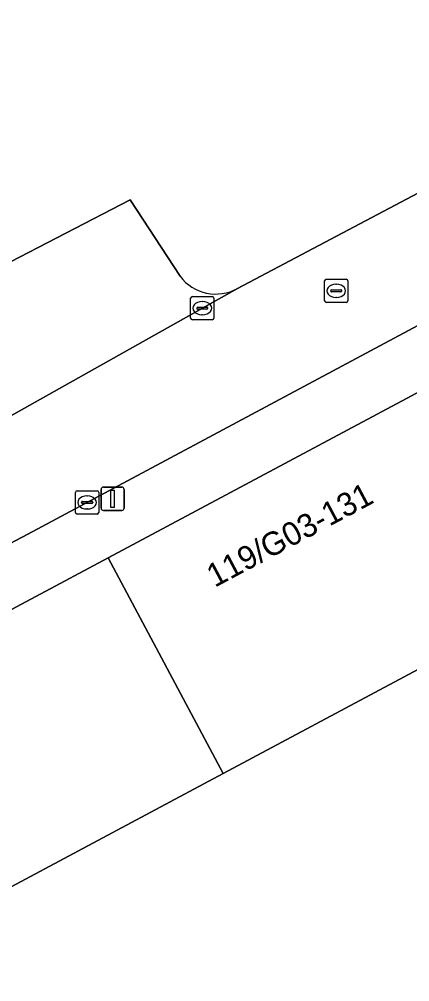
# Model space of a CAD drawing. Extents: x 159674 to 160531, y 382172 to 382904.
# Drawn here: x 159950.09 to 159966.84, y 382325.17 to 382366.41 of the extents above; entities that cross this region are included whole.
import ezdxf

# ---------------------------------------------------------------- set-up
doc = ezdxf.new("R2010")
doc.units = 0
for name, color, linetype in [('IMGEO_Groenvoorziening', 7, 'Continuous'), ('IMGEO_Kolk', 7, 'Continuous'), ('IMGEO_Lichtmast', 7, 'Continuous'), ('IMGEO_Pand', 7, 'Continuous'), ('IMGEO_Pand_nummerreeks', 7, 'Continuous'), ('IMGEO_Parkeervlak_open', 7, 'Continuous'), ('IMGEO_Rijbaan_lokaal_open', 7, 'Continuous'), ('IMGEO_Rioolput', 7, 'Continuous'), ('IMGEO_Voetpad_open', 7, 'Continuous')]:
    doc.layers.add(name, color=color, linetype=linetype)

msp = doc.modelspace()

# ---------------------------------------------------------------- linework, layer by layer
at = {"layer": 'IMGEO_Groenvoorziening'}
for points in [[(160033.982, 382351.425), (160006.646, 382371.299), (160000.468, 382368.176), (160005.403, 382358.937), (160000, 382356.044), (159989.896, 382350.653), (159974.368, 382342.369), (159958.839, 382334.084), (159943.311, 382325.8), (159938.381, 382335.041), (159938.238, 382335.298), (159928.126, 382329.843), (159949.672, 382314.284), (159964.599, 382303.191), (159975.985, 382309.171), (159974.461, 382312.133), (159975.28, 382312.603), (159974.356, 382314.464), (159976.287, 382315.345), (159977.115, 382313.657), (159977.738, 382314.014)], [(159959.456, 382354.877), (159977.713, 382364.513)], [(159940.529, 382347.836), (159937.53, 382354.114), (159941.863, 382356.347), (159943.794, 382352.965), (159954.842, 382358.673), (159956.987, 382355.398)]]:
    msp.add_lwpolyline(points, dxfattribs=at)
msp.add_arc((159958.524, 382356.57), 1.933, 217.338, 298.8308, dxfattribs=at)
at = {"layer": 'IMGEO_Kolk'}
for p, q in [((159957.443, 382353.605), (159957.443, 382354.457)), ((159957.518, 382354.531), (159958.37, 382354.531)), ((159957.931, 382354.311), (159957.956, 382354.311)), ((159958.444, 382354.457), (159958.444, 382353.605)), ((159957.702, 382354.025), (159957.702, 382354.037)), ((159958.14, 382353.988), (159957.742, 382353.988)), ((159957.745, 382354.074), (159958.143, 382354.074)), ((159957.954, 382353.751), (159957.929, 382353.751)), ((159958.186, 382354.037), (159958.186, 382354.025)), ((159958.37, 382353.531), (159957.518, 382353.531)), ((159952.5, 382345.28), (159952.5, 382346.132)), ((159952.575, 382346.206), (159953.427, 382346.206)), ((159952.988, 382345.986), (159953.013, 382345.986)), ((159953.501, 382346.132), (159953.501, 382345.28)), ((159952.759, 382345.7), (159952.759, 382345.712)), ((159953.197, 382345.663), (159952.799, 382345.663)), ((159952.802, 382345.749), (159953.2, 382345.749)), ((159953.243, 382345.712), (159953.243, 382345.7)), ((159953.427, 382345.206), (159952.575, 382345.206)), ((159953.011, 382345.426), (159952.986, 382345.426))]:
    msp.add_line(p, q, dxfattribs=at)
for points in [[(159957.443, 382353.605), (159957.443, 382354.457)], [(159957.518, 382354.531), (159958.37, 382354.531)], [(159958.444, 382354.457), (159958.444, 382353.605)], [(159958.37, 382353.531), (159957.518, 382353.531)], [(159952.5, 382345.28), (159952.5, 382346.132)], [(159952.575, 382346.206), (159953.427, 382346.206)], [(159953.501, 382346.132), (159953.501, 382345.28)], [(159953.427, 382345.206), (159952.575, 382345.206)]]:
    msp.add_lwpolyline(points, dxfattribs=at)
for centre, radius, start, end in [((159957.52, 382354.455), 0.0765, 91.552, 178.448), ((159957.52, 382354.455), 0.0765, 91.552, 178.448), ((159958.368, 382354.455), 0.0765, 1.552, 88.448), ((159958.368, 382354.455), 0.0765, 1.552, 88.448), ((159957.742, 382354.034), 0.0403, 85.8775, 175.7526), ((159957.739, 382354.024), 0.0366, 178.938, 274.7102), ((159958.143, 382354.031), 0.043, 264.8664, 352.4533), ((159958.147, 382354.036), 0.0386, 1.7309, 96.639), ((159957.52, 382353.607), 0.0765, 181.552, 268.448), ((159957.52, 382353.607), 0.0765, 181.552, 268.448), ((159958.368, 382353.607), 0.0765, 271.552, 358.448), ((159958.368, 382353.607), 0.0765, 271.552, 358.448), ((159952.577, 382346.13), 0.0765, 91.552, 178.448), ((159952.577, 382346.13), 0.0765, 91.552, 178.448), ((159953.425, 382346.13), 0.0765, 1.552, 88.448), ((159953.425, 382346.13), 0.0765, 1.552, 88.448), ((159952.799, 382345.709), 0.0403, 85.8775, 175.7526), ((159952.796, 382345.699), 0.0366, 178.938, 274.7102), ((159953.2, 382345.706), 0.043, 264.8664, 352.4533), ((159953.204, 382345.711), 0.0386, 1.7309, 96.639), ((159952.577, 382345.282), 0.0765, 181.552, 268.448), ((159952.577, 382345.282), 0.0765, 181.552, 268.448), ((159953.425, 382345.282), 0.0765, 271.552, 358.448), ((159953.425, 382345.282), 0.0765, 271.552, 358.448)]:
    msp.add_arc(centre, radius, start, end, dxfattribs=at)
for centre, major_axis, ratio, start_param, end_param in [((159957.93, 382354.031), (-0.387, 0.002), 0.722429, 4.712389, 7.853982), ((159957.955, 382354.031), (-0.39, 0.002), 0.717154, 1.570796, 4.712389), ((159952.987, 382345.706), (-0.387, 0.002), 0.722429, 4.712389, 7.853982), ((159953.012, 382345.706), (-0.39, 0.002), 0.717154, 1.570796, 4.712389)]:
    msp.add_ellipse(centre, major_axis=major_axis, ratio=ratio, start_param=start_param, end_param=end_param, dxfattribs=at)
at = {"layer": 'IMGEO_Lichtmast'}
for p, q in [((159953.698, 382346.363), (159954.488, 382346.363)), ((159954.488, 382346.363), (159953.698, 382346.363)), ((159953.598, 382345.463), (159953.598, 382346.263)), ((159953.598, 382346.263), (159953.598, 382345.463)), ((159954.588, 382346.263), (159954.588, 382345.463)), ((159954.588, 382345.463), (159954.588, 382346.263)), ((159954.488, 382345.363), (159953.698, 382345.363)), ((159953.698, 382345.363), (159954.488, 382345.363))]:
    msp.add_line(p, q, dxfattribs=at)
msp.add_lwpolyline([(159954.018, 382346.238), (159954.168, 382346.238), (159954.168, 382345.488), (159954.018, 382345.488), (159954.018, 382346.238)], dxfattribs=at)
for centre, start, end in [((159953.698, 382346.263), 90, 180), ((159953.698, 382346.263), 90, 180), ((159954.488, 382346.263), 0, 90), ((159954.488, 382346.263), 360, 90), ((159953.698, 382345.463), 180, 270), ((159953.698, 382345.463), 180, 270), ((159954.488, 382345.463), 270, 0), ((159954.488, 382345.463), 270, 0)]:
    msp.add_arc(centre, 0.1, start, end, dxfattribs=at)
at = {"layer": 'IMGEO_Pand'}
for points in [[(159974.368, 382342.369), (159969.437, 382351.61), (159953.909, 382343.326), (159958.839, 382334.084)], [(159953.909, 382343.326), (159938.381, 382335.041), (159943.311, 382325.8), (159958.839, 382334.084)]]:
    msp.add_lwpolyline(points, close=True, dxfattribs=at)
at = {"layer": 'IMGEO_Parkeervlak_open'}
for points in [[(159956.987, 382355.398), (159954.842, 382358.673), (159943.794, 382352.965), (159941.863, 382356.347), (159937.53, 382354.114), (159940.529, 382347.836)], [(159940.896, 382344.598), (159949.034, 382349.036), (159959.456, 382354.877)]]:
    msp.add_lwpolyline(points, dxfattribs=at)
msp.add_arc((159958.524, 382356.57), 1.933, 217.338, 298.8308, dxfattribs=at)
at = {"layer": 'IMGEO_Rijbaan_lokaal_open'}
for points in [[(159985.145, 382368.436), (159979.562, 382365.489), (159977.713, 382364.513), (159959.456, 382354.877), (159949.034, 382349.036), (159940.896, 382344.598)], [(159938.868, 382342.054), (159935.493, 382340.283), (159937.083, 382337.299), (159950.454, 382344.344), (159985.984, 382363.33)]]:
    msp.add_lwpolyline(points, dxfattribs=at)
at = {"layer": 'IMGEO_Rioolput'}
for p, q in [((159963.189, 382354.348), (159963.189, 382355.2)), ((159963.264, 382355.274), (159964.116, 382355.274)), ((159963.677, 382355.054), (159963.702, 382355.054)), ((159964.19, 382355.2), (159964.19, 382354.348)), ((159963.448, 382354.768), (159963.448, 382354.78)), ((159963.886, 382354.731), (159963.488, 382354.731)), ((159963.491, 382354.817), (159963.889, 382354.817)), ((159963.932, 382354.78), (159963.932, 382354.768)), ((159964.116, 382354.274), (159963.264, 382354.274)), ((159963.7, 382354.494), (159963.675, 382354.494))]:
    msp.add_line(p, q, dxfattribs=at)
for points in [[(159963.189, 382354.348), (159963.189, 382355.2)], [(159963.264, 382355.274), (159964.116, 382355.274)], [(159964.19, 382355.2), (159964.19, 382354.348)], [(159964.116, 382354.274), (159963.264, 382354.274)]]:
    msp.add_lwpolyline(points, dxfattribs=at)
for centre, radius, start, end in [((159963.266, 382355.198), 0.0765, 91.552, 178.448), ((159963.266, 382355.198), 0.0765, 91.552, 178.448), ((159964.114, 382355.198), 0.0765, 1.552, 88.448), ((159964.114, 382355.198), 0.0765, 1.552, 88.448), ((159963.488, 382354.777), 0.0403, 85.8775, 175.7526), ((159963.485, 382354.767), 0.0366, 178.938, 274.7102), ((159963.889, 382354.774), 0.043, 264.8664, 352.4533), ((159963.893, 382354.779), 0.0386, 1.7309, 96.639), ((159963.266, 382354.35), 0.0765, 181.552, 268.448), ((159963.266, 382354.35), 0.0765, 181.552, 268.448), ((159964.114, 382354.35), 0.0765, 271.552, 358.448), ((159964.114, 382354.35), 0.0765, 271.552, 358.448)]:
    msp.add_arc(centre, radius, start, end, dxfattribs=at)
for centre, major_axis, ratio, start_param, end_param in [((159963.676, 382354.774), (-0.387, 0.002), 0.722429, 4.712389, 7.853982), ((159963.701, 382354.774), (-0.39, 0.002), 0.717154, 1.570796, 4.712389)]:
    msp.add_ellipse(centre, major_axis=major_axis, ratio=ratio, start_param=start_param, end_param=end_param, dxfattribs=at)
at = {"layer": 'IMGEO_Voetpad_open'}
msp.add_lwpolyline([(159985.984, 382363.33), (159950.454, 382344.344), (159937.083, 382337.299), (159925.951, 382331.335), (159928.126, 382329.843), (159938.238, 382335.298), (159938.381, 382335.041), (159953.909, 382343.326), (159969.437, 382351.61), (159984.966, 382359.895), (160000, 382367.916), (160000.468, 382368.176), (160006.646, 382371.299), (160000.044, 382376.097)], dxfattribs=at)

# ---------------------------------------------------------------- texts
at = {"layer": 'IMGEO_Pand_nummerreeks'}
msp.add_text('119/G03-131', height=1, rotation=28.0808, dxfattribs=at).set_placement((159958.476, 382342.044))

doc.saveas('drawing.dxf')
